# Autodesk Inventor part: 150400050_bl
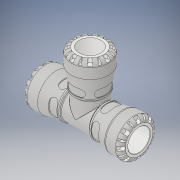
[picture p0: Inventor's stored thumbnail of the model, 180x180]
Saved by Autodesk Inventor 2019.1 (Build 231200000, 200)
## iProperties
Created: 2016-12
Part Number: 150400050_bl
Material: Generic
Description: PLASSON G-PLASS TEE 50X50X50
Document SubType Name: Modeling
Designer: KIM
Mass: 664.223 g
Surface Area: 733.008 cm^2
Volume: 474.445 cm^3
Density: 1 g/cm^3
Appearance: Default
Author: KIM
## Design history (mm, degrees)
derived "150400.ipt"
feature "Solid1::150400.ipt" dims "ScaleForDerivedMember" = 10
tag "TaggingFeature1"
body "Solid1"
other parameters: "E_" = 85 [user parameter], "l_" = 83 [user parameter], "A_" = 128 [user parameter], "H_" = 223 [user parameter], "d9" = 11.25 [user parameter], "d11" = 85 [user parameter], "d12" = 62.5 [user parameter], "d230" = 85 [user parameter], "d231" = 62.5 [user parameter], "d232" = 11.25 [user parameter], "d1" = 34.86 [user parameter], "d3" = 62.5 [user parameter], "d4" = 85 [user parameter], "d8" = 72.25 [user parameter], "d13" = 9 [user parameter], "d14" = 9 [user parameter], "d15" = 0 [user parameter], "d17" = 360 deg [user parameter], "d19" = 8 deg [user parameter], "d20" = 1 [user parameter], "d21" = 1 [user parameter], "d22" = 8 deg [user parameter], "d24" = 0 [user parameter], "d26" = 360 deg [user parameter], "d33" = 8.5 [user parameter], "d43" = 66.3 [user parameter], "d51" = 0.85 [user parameter], "d54" = 17.5 [user parameter], "d55" = 11 [user parameter], "d57" = 17.64 [user parameter], "d58" = 0 [user parameter], "d74" = 0 [user parameter], "d77" = 4.16667 [user parameter], "d78" = 83 [user parameter], "d79" = 66.3 [user parameter], "d80" = 223 [user parameter], "d82" = 1 [user parameter], "d115" = 360 deg [user parameter], "d139" = 9 [user parameter], "d140" = 0 [user parameter], "d142" = 360 deg [user parameter], "d207" = 90 deg [user parameter], "d209" = 34.86 [user parameter], "d211" = 62.5 [user parameter], "d212" = 85 [user parameter], "d213" = 72.25 [user parameter], "d215" = 66.3 [user parameter], "d216" = 4.16667 [user parameter], "d217" = 83 [user parameter], "d225" = 128 [user parameter], "d226" = 83 [user parameter], "d228" = 14.875 [user parameter], "d229" = 9 [user parameter], "d233" = 9 [user parameter], "d234" = 0 [user parameter], "d236" = 360 deg [user parameter], "d238" = 8 deg [user parameter], "d239" = 8 deg [user parameter], "d240" = 1 [user parameter], "d241" = 1 [user parameter], "d243" = 0 [user parameter], "d245" = 360 deg [user parameter], "d247" = 1.7 [user parameter], "d248" = 4.98 [user parameter], "d249" = 4.98 [user parameter], "d250" = 14.875 [user parameter], "d252" = 17.5 [user parameter], "d253" = 11.5 [user parameter], "d254" = 17.64 [user parameter], "d255" = 0 [user parameter], "d257" = 360 deg [user parameter], "d259" = 1 [user parameter], "d261" = 0 [user parameter], "d262" = 1.7 [user parameter], "d264" = 0 [user parameter], "d266" = 0 [user parameter], "d267" = 0.85 [user parameter]
